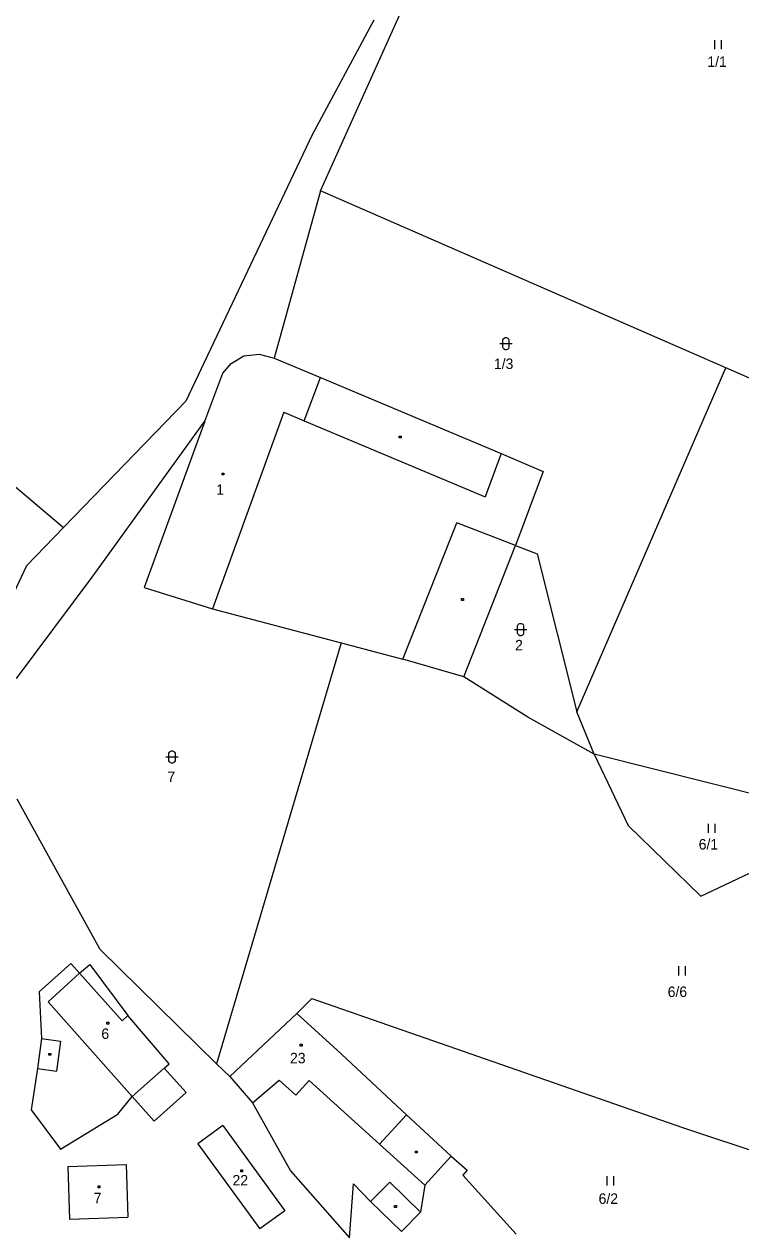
# Model space of a CAD drawing. Extents: x -794421 to -792735, y -1117671 to -1115559.
# Drawn here: x -793405.9 to -793289.6, y -1116892.5 to -1116696.2 of the extents above; entities that cross this region are included whole.
import ezdxf

# ---------------------------------------------------------------- set-up
doc = ezdxf.new("R2010")
doc.units = 0
for name, color, linetype in [('Vrstva 1', 7, 'Continuous'), ('Vrstva 14', 7, 'Continuous'), ('Vrstva 15', 7, 'Continuous'), ('Vrstva 2', 7, 'Continuous'), ('Vrstva 23', 7, 'Continuous'), ('Vrstva 25', 7, 'Continuous')]:
    doc.layers.add(name, color=color, linetype=linetype)

msp = doc.modelspace()

# ---------------------------------------------------------------- linework, layer by layer
at = {"layer": 'Vrstva 1'}
for p, q in [((-793357.85, -1116723.31), (-793344.69, -1116694.05)), ((-793349.18, -1116695.56), (-793359.19, -1116714.22)), ((-793359.19, -1116714.22), (-793379.68, -1116757.45)), ((-793357.85, -1116723.31), (-793365.33, -1116750.45)), ((-793292.01, -1116752.03), (-793357.85, -1116723.31)), ((-793373.7, -1116752.92), (-793372.34, -1116751.36)), ((-793372.34, -1116751.36), (-793370.26, -1116750.11)), ((-793370.26, -1116750.11), (-793367.76, -1116749.8)), ((-793367.76, -1116749.8), (-793365.33, -1116750.45)), ((-793365.33, -1116750.45), (-793357.81, -1116753.62)), ((-793376.63, -1116760.69), (-793373.7, -1116752.92)), ((-793316.21, -1116807.9), (-793292.01, -1116752.03)), ((-793259.64, -1116766.35), (-793292.01, -1116752.03)), ((-793357.81, -1116753.62), (-793328.47, -1116765.98)), ((-793379.68, -1116757.45), (-793399.55, -1116777.99)), ((-793394.89, -1116786.04), (-793376.63, -1116760.69)), ((-793376.63, -1116760.69), (-793386.45, -1116787.75)), ((-793328.47, -1116765.98), (-793321.64, -1116768.86)), ((-793409.92, -1116769.28), (-793399.55, -1116777.99)), ((-793321.64, -1116768.86), (-793326.15, -1116780.9)), ((-793399.55, -1116777.99), (-793405.56, -1116784.23)), ((-793334.56, -1116802.26), (-793326.15, -1116780.9)), ((-793326.15, -1116780.9), (-793322.62, -1116782.25)), ((-793322.62, -1116782.25), (-793316.21, -1116807.9)), ((-793405.56, -1116784.23), (-793414.95, -1116803.81)), ((-793407.19, -1116802.49), (-793394.89, -1116786.04)), ((-793386.45, -1116787.75), (-793375.36, -1116791.2)), ((-793375.36, -1116791.2), (-793354.48, -1116796.7)), ((-793354.48, -1116796.7), (-793374.72, -1116865.1)), ((-793354.48, -1116796.7), (-793344.46, -1116799.34)), ((-793334.56, -1116802.26), (-793344.46, -1116799.34)), ((-793324.13, -1116808.77), (-793334.56, -1116802.26)), ((-793313.38, -1116814.8), (-793316.21, -1116807.9)), ((-793313.38, -1116814.8), (-793324.13, -1116808.77)), ((-793273.14, -1116824.93), (-793313.38, -1116814.8)), ((-793313.38, -1116814.8), (-793307.87, -1116826.39)), ((-793393.6, -1116846.5), (-793407.1, -1116822.08)), ((-793307.87, -1116826.39), (-793296.06, -1116837.88)), ((-793296.06, -1116837.88), (-793281.23, -1116830.79)), ((-793374.72, -1116865.1), (-793393.6, -1116846.5)), ((-793403.5, -1116853.42), (-793398.36, -1116848.78)), ((-793396.95, -1116850.37), (-793398.36, -1116848.78)), ((-793396.95, -1116850.37), (-793395.28, -1116848.95)), ((-793395.28, -1116848.95), (-793389.14, -1116857.23)), ((-793403.5, -1116853.42), (-793403.11, -1116860.98)), ((-793361.68, -1116856.89), (-793359.25, -1116854.46)), ((-793359.25, -1116854.46), (-793299.01, -1116875.45)), ((-793382.42, -1116865.08), (-793389.14, -1116857.23)), ((-793361.68, -1116856.89), (-793372.55, -1116867.16)), ((-793355.15, -1116862.82), (-793361.68, -1116856.89)), ((-793403.11, -1116860.98), (-793403.79, -1116865.83)), ((-793343.86, -1116873.39), (-793355.15, -1116862.82)), ((-793383.19, -1116865.77), (-793382.42, -1116865.08)), ((-793374.72, -1116865.1), (-793372.55, -1116867.16)), ((-793403.79, -1116865.83), (-793404.79, -1116872.55)), ((-793379.63, -1116869.76), (-793383.19, -1116865.77)), ((-793372.55, -1116867.16), (-793368.85, -1116871.42)), ((-793390.75, -1116873.29), (-793388.4, -1116870.4)), ((-793388.4, -1116870.4), (-793384.84, -1116874.39)), ((-793384.84, -1116874.39), (-793379.63, -1116869.76)), ((-793404.79, -1116872.55), (-793400.03, -1116878.94)), ((-793400.03, -1116878.94), (-793390.75, -1116873.29)), ((-793368.85, -1116871.42), (-793362.68, -1116882.48)), ((-793373.68, -1116875.13), (-793377.72, -1116878.07)), ((-793373.68, -1116875.13), (-793363.62, -1116888.97)), ((-793343.86, -1116873.39), (-793336.62, -1116880.11)), ((-793299.01, -1116875.45), (-793275.69, -1116883.23)), ((-793377.72, -1116878.07), (-793367.67, -1116891.91)), ((-793336.62, -1116880.11), (-793340.9, -1116884.82)), ((-793336.62, -1116880.11), (-793334.01, -1116882.36)), ((-793398.86, -1116881.75), (-793389.37, -1116881.46)), ((-793398.86, -1116881.75), (-793398.61, -1116890.3)), ((-793389.37, -1116881.46), (-793389.11, -1116890.01)), ((-793362.68, -1116882.48), (-793353.13, -1116893.37)), ((-793334.01, -1116882.36), (-793334.69, -1116883.19)), ((-793353.13, -1116893.37), (-793352.44, -1116884.6)), ((-793352.44, -1116884.6), (-793349.71, -1116887.43)), ((-793340.9, -1116884.82), (-793341.6, -1116889.18)), ((-793334.69, -1116883.19), (-793326.03, -1116892.76)), ((-793363.62, -1116888.97), (-793367.67, -1116891.91)), ((-793344.65, -1116892.32), (-793349.71, -1116887.43)), ((-793398.61, -1116890.3), (-793389.11, -1116890.01)), ((-793341.6, -1116889.18), (-793344.65, -1116892.32))]:
    msp.add_line(p, q, dxfattribs=at)
at = {"layer": 'Vrstva 2'}
for p, q in [((-793360.46, -1116760.64), (-793357.81, -1116753.62)), ((-793363.76, -1116759.25), (-793375.36, -1116791.2)), ((-793363.76, -1116759.25), (-793360.46, -1116760.64)), ((-793360.46, -1116760.64), (-793331.1, -1116773.01)), ((-793328.47, -1116765.98), (-793331.1, -1116773.01)), ((-793344.46, -1116799.34), (-793335.67, -1116777.2)), ((-793326.15, -1116780.9), (-793335.67, -1116777.2)), ((-793402.08, -1116855), (-793396.95, -1116850.37)), ((-793396.95, -1116850.37), (-793390.05, -1116858.13)), ((-793402.08, -1116855), (-793388.4, -1116870.4)), ((-793390.05, -1116858.13), (-793389.14, -1116857.23)), ((-793403.11, -1116860.98), (-793400.04, -1116861.41)), ((-793400.04, -1116861.41), (-793400.72, -1116866.26)), ((-793403.79, -1116865.83), (-793400.72, -1116866.26)), ((-793388.4, -1116870.4), (-793383.19, -1116865.77)), ((-793368.85, -1116871.42), (-793364.54, -1116867.72)), ((-793364.54, -1116867.72), (-793361.83, -1116870.18)), ((-793361.83, -1116870.18), (-793359.65, -1116867.78)), ((-793359.65, -1116867.78), (-793348.24, -1116878.15)), ((-793348.24, -1116878.15), (-793343.86, -1116873.39)), ((-793340.9, -1116884.82), (-793348.24, -1116878.15)), ((-793346.59, -1116884.32), (-793349.71, -1116887.43)), ((-793341.6, -1116889.18), (-793346.59, -1116884.32))]:
    msp.add_line(p, q, dxfattribs=at)
at = {"layer": 'Vrstva 23'}
for p, q in [((-793293.77, -1116700.31), (-793293.77, -1116698.81)), ((-793292.77, -1116698.81), (-793292.77, -1116700.31)), ((-793328.21, -1116747.51), (-793328.11, -1116747.31)), ((-793328.21, -1116748.71), (-793328.21, -1116747.51)), ((-793328.11, -1116747.31), (-793328.01, -1116747.21)), ((-793328.01, -1116747.21), (-793327.81, -1116747.11)), ((-793327.81, -1116747.11), (-793327.61, -1116747.11)), ((-793327.61, -1116747.11), (-793327.41, -1116747.21)), ((-793327.41, -1116747.21), (-793327.31, -1116747.31)), ((-793327.31, -1116747.31), (-793327.21, -1116747.51)), ((-793327.21, -1116747.51), (-793327.21, -1116748.71)), ((-793328.71, -1116748.11), (-793326.71, -1116748.11)), ((-793328.11, -1116748.91), (-793328.21, -1116748.71)), ((-793328.01, -1116749.01), (-793328.11, -1116748.91)), ((-793327.81, -1116749.11), (-793328.01, -1116749.01)), ((-793327.61, -1116749.11), (-793327.81, -1116749.11)), ((-793327.41, -1116749.01), (-793327.61, -1116749.11)), ((-793327.31, -1116748.91), (-793327.41, -1116749.01)), ((-793327.21, -1116748.71), (-793327.31, -1116748.91)), ((-793326.33, -1116794.55), (-793324.33, -1116794.55)), ((-793325.83, -1116793.95), (-793325.73, -1116793.75)), ((-793325.83, -1116795.15), (-793325.83, -1116793.95)), ((-793325.73, -1116793.75), (-793325.63, -1116793.65)), ((-793325.63, -1116793.65), (-793325.43, -1116793.55)), ((-793325.43, -1116793.55), (-793325.23, -1116793.55)), ((-793325.23, -1116793.55), (-793325.03, -1116793.65)), ((-793325.03, -1116793.65), (-793324.93, -1116793.75)), ((-793324.93, -1116793.75), (-793324.83, -1116793.95)), ((-793324.83, -1116793.95), (-793324.83, -1116795.15)), ((-793325.73, -1116795.35), (-793325.83, -1116795.15)), ((-793325.63, -1116795.45), (-793325.73, -1116795.35)), ((-793325.43, -1116795.55), (-793325.63, -1116795.45)), ((-793325.23, -1116795.55), (-793325.43, -1116795.55)), ((-793325.03, -1116795.45), (-793325.23, -1116795.55)), ((-793324.93, -1116795.35), (-793325.03, -1116795.45)), ((-793324.83, -1116795.15), (-793324.93, -1116795.35)), ((-793382.33, -1116814.45), (-793382.23, -1116814.35)), ((-793382.23, -1116814.35), (-793382.03, -1116814.25)), ((-793382.03, -1116814.25), (-793381.83, -1116814.25)), ((-793381.83, -1116814.25), (-793381.63, -1116814.35)), ((-793381.63, -1116814.35), (-793381.53, -1116814.45)), ((-793382.93, -1116815.25), (-793380.93, -1116815.25)), ((-793382.43, -1116814.65), (-793382.33, -1116814.45)), ((-793382.43, -1116815.85), (-793382.43, -1116814.65)), ((-793382.33, -1116816.05), (-793382.43, -1116815.85)), ((-793382.23, -1116816.15), (-793382.33, -1116816.05)), ((-793382.03, -1116816.25), (-793382.23, -1116816.15)), ((-793381.83, -1116816.25), (-793382.03, -1116816.25)), ((-793381.63, -1116816.15), (-793381.83, -1116816.25)), ((-793381.53, -1116816.05), (-793381.63, -1116816.15)), ((-793381.53, -1116814.45), (-793381.43, -1116814.65)), ((-793381.43, -1116815.85), (-793381.53, -1116816.05)), ((-793381.43, -1116814.65), (-793381.43, -1116815.85)), ((-793294.8, -1116827.59), (-793294.8, -1116826.09)), ((-793293.8, -1116826.09), (-793293.8, -1116827.59)), ((-793299.61, -1116850.75), (-793299.61, -1116849.25)), ((-793298.61, -1116849.25), (-793298.61, -1116850.75)), ((-793311.24, -1116884.85), (-793311.24, -1116883.35)), ((-793310.24, -1116883.35), (-793310.24, -1116884.85))]:
    msp.add_line(p, q, dxfattribs=at)
at = {"layer": 'Vrstva 25'}
for p, q in [((-793345.03, -1116763.12), (-793344.73, -1116763.12)), ((-793345.03, -1116763.42), (-793345.03, -1116763.12)), ((-793344.73, -1116763.12), (-793344.73, -1116763.42)), ((-793344.73, -1116763.42), (-793345.03, -1116763.42)), ((-793373.81, -1116769.15), (-793373.51, -1116769.15)), ((-793373.81, -1116769.45), (-793373.81, -1116769.15)), ((-793373.51, -1116769.15), (-793373.51, -1116769.45)), ((-793373.51, -1116769.45), (-793373.81, -1116769.45)), ((-793334.9, -1116789.51), (-793334.6, -1116789.51)), ((-793334.9, -1116789.81), (-793334.9, -1116789.51)), ((-793334.6, -1116789.81), (-793334.9, -1116789.81)), ((-793334.6, -1116789.51), (-793334.6, -1116789.81)), ((-793392.51, -1116858.35), (-793392.21, -1116858.35)), ((-793392.51, -1116858.65), (-793392.51, -1116858.35)), ((-793392.21, -1116858.65), (-793392.51, -1116858.65)), ((-793392.21, -1116858.35), (-793392.21, -1116858.65)), ((-793401.92, -1116863.39), (-793401.62, -1116863.39)), ((-793401.92, -1116863.69), (-793401.92, -1116863.39)), ((-793401.62, -1116863.39), (-793401.62, -1116863.69)), ((-793361.12, -1116861.92), (-793360.82, -1116861.92)), ((-793361.12, -1116862.22), (-793361.12, -1116861.92)), ((-793360.82, -1116862.22), (-793361.12, -1116862.22)), ((-793360.82, -1116861.92), (-793360.82, -1116862.22)), ((-793401.62, -1116863.69), (-793401.92, -1116863.69)), ((-793342.41, -1116879.25), (-793342.11, -1116879.25)), ((-793342.41, -1116879.55), (-793342.41, -1116879.25)), ((-793342.11, -1116879.55), (-793342.41, -1116879.55)), ((-793342.11, -1116879.25), (-793342.11, -1116879.55)), ((-793370.78, -1116882.33), (-793370.48, -1116882.33)), ((-793370.78, -1116882.63), (-793370.78, -1116882.33)), ((-793370.48, -1116882.63), (-793370.78, -1116882.63)), ((-793370.48, -1116882.33), (-793370.48, -1116882.63)), ((-793393.94, -1116884.92), (-793393.64, -1116884.92)), ((-793393.94, -1116885.22), (-793393.94, -1116884.92)), ((-793393.64, -1116884.92), (-793393.64, -1116885.22)), ((-793393.64, -1116885.22), (-793393.94, -1116885.22)), ((-793345.79, -1116888.11), (-793345.49, -1116888.11)), ((-793345.79, -1116888.41), (-793345.79, -1116888.11)), ((-793345.49, -1116888.41), (-793345.79, -1116888.41)), ((-793345.49, -1116888.11), (-793345.49, -1116888.41))]:
    msp.add_line(p, q, dxfattribs=at)

# ---------------------------------------------------------------- texts
at = {"layer": 'Vrstva 14'}
for s, p in [('1/1', (-793294.997, -1116703.16)), ('1/3', (-793329.663, -1116752.23)), ('2', (-793326.217, -1116797.93)), ('7', (-793382.683, -1116819.31)), ('6/1', (-793296.403, -1116830.28)), ('6/6', (-793301.44, -1116854.23)), ('6/2', (-793312.66, -1116887.84))]:
    msp.add_text(s, height=1.7, dxfattribs=at).set_placement(p)
at = {"layer": 'Vrstva 15'}
for s, p in [('1', (-793374.75, -1116772.66)), ('6', (-793393.417, -1116861.05)), ('23', (-793362.777, -1116865.01)), ('22', (-793372.116, -1116884.85)), ('7', (-793394.653, -1116887.74))]:
    msp.add_text(s, height=1.7, dxfattribs=at).set_placement(p)

doc.saveas('drawing.dxf')
